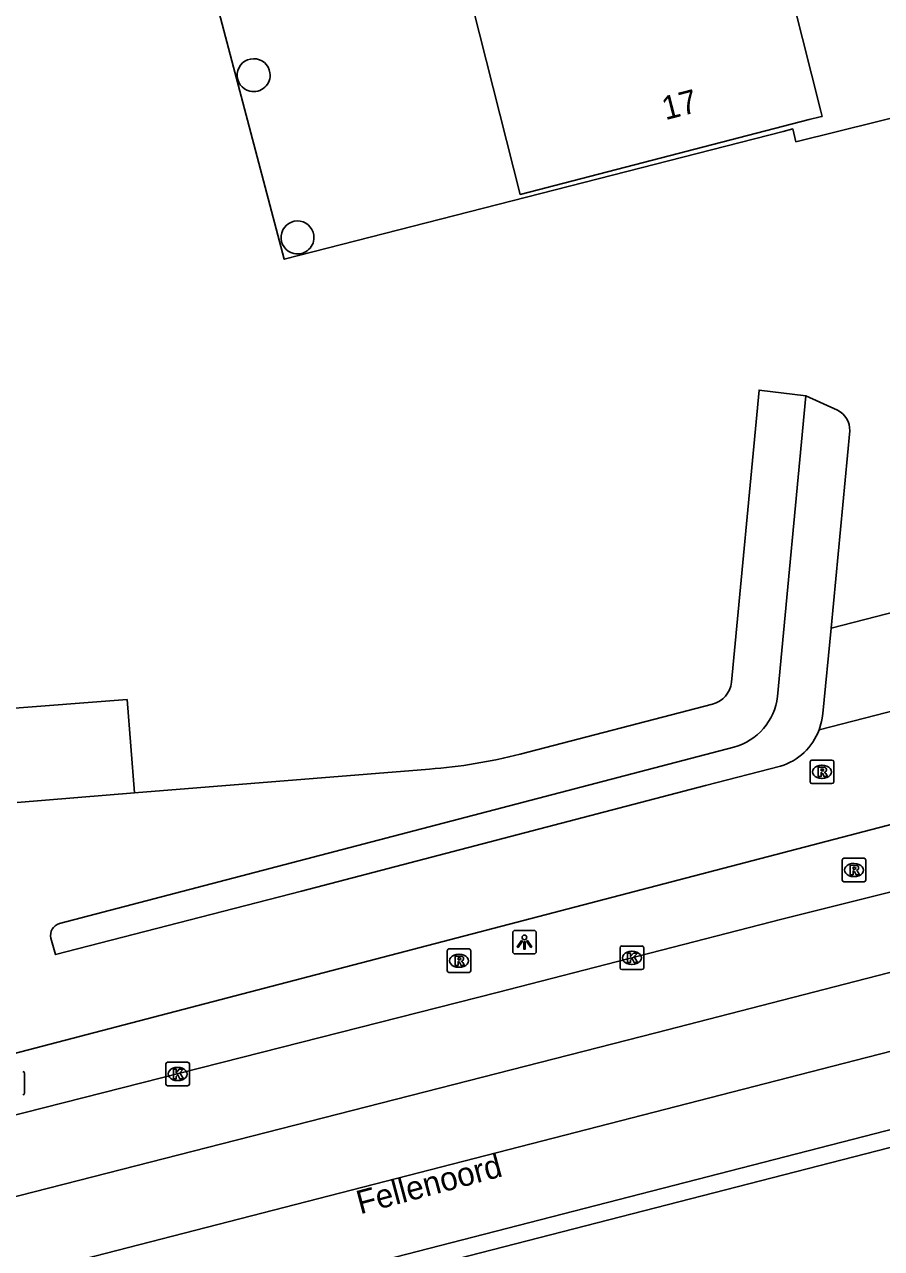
# Model space of a CAD drawing. Extents: x 160806 to 161707, y 383697 to 384148.
# Drawn here: x 161279.8 to 161316.2, y 383941 to 383993.1 of the extents above; entities that cross this region are included whole.
import ezdxf

# ---------------------------------------------------------------- set-up
doc = ezdxf.new("R2010")
doc.units = 0
for name, color, linetype in [('IMGEO_Groenvoorziening', 7, 'Continuous'), ('IMGEO_Hek', 7, 'Continuous'), ('IMGEO_Kolk', 7, 'Continuous'), ('IMGEO_Lichtpunt', 7, 'Continuous'), ('IMGEO_Openbare_ruimte_label', 7, 'Continuous'), ('IMGEO_Pand', 7, 'Continuous'), ('IMGEO_Pand_nummerreeks', 7, 'Continuous'), ('IMGEO_Pand_overbouw', 7, 'Continuous'), ('IMGEO_Rijbaan_lokaal_gesloten', 7, 'Continuous'), ('IMGEO_Rioolput', 7, 'Continuous'), ('IMGEO_Voetpad_gesloten', 7, 'Continuous'), ('IMGEO_Voetpad_op_trap', 7, 'Continuous'), ('IMGEO_Voetpad_open', 7, 'Continuous')]:
    doc.layers.add(name, color=color, linetype=linetype)

msp = doc.modelspace()

# ---------------------------------------------------------------- linework, layer by layer
at = {"layer": 'IMGEO_Groenvoorziening'}
for points in [[(161312.991, 383977.283), (161314.329, 383976.67)], [(161314.852, 383975.798), (161314.058, 383967.401)]]:
    msp.add_lwpolyline(points, dxfattribs=at)
msp.add_arc((161313.922, 383975.833), 0.931, 357.8367, 64.0715, dxfattribs=at)
at = {"layer": 'IMGEO_Hek'}
msp.add_lwpolyline([(161341.247, 383951.682), (161296.689, 383940.215), (161287.043, 383937.692)], dxfattribs=at)
at = {"layer": 'IMGEO_Kolk'}
for p, q in [((161305.096, 383952.97), (161305.096, 383953.822)), ((161305.171, 383953.896), (161306.023, 383953.896)), ((161306.097, 383953.822), (161306.097, 383952.97)), ((161305.584, 383953.676), (161305.609, 383953.676)), ((161306.023, 383952.896), (161305.171, 383952.896)), ((161305.607, 383953.116), (161305.582, 383953.116)), ((161285.793, 383948.03), (161285.793, 383948.882)), ((161285.868, 383948.956), (161286.72, 383948.956)), ((161286.281, 383948.736), (161286.306, 383948.736)), ((161286.794, 383948.882), (161286.794, 383948.03)), ((161286.304, 383948.176), (161286.279, 383948.176)), ((161286.72, 383947.956), (161285.868, 383947.956))]:
    msp.add_line(p, q, dxfattribs=at)
for points in [[(161305.096, 383952.97), (161305.096, 383953.822)], [(161305.171, 383953.896), (161306.023, 383953.896)], [(161306.097, 383953.822), (161306.097, 383952.97)], [(161305.417, 383953.596), (161305.54, 383953.596), (161305.54, 383953.445), (161305.67, 383953.596), (161305.834, 383953.596), (161305.688, 383953.445), (161305.841, 383953.196), (161305.689, 383953.196), (161305.604, 383953.36), (161305.54, 383953.293), (161305.54, 383953.196), (161305.417, 383953.196), (161305.417, 383953.596)], [(161306.023, 383952.896), (161305.171, 383952.896)], [(161285.793, 383948.03), (161285.793, 383948.882)], [(161285.868, 383948.956), (161286.72, 383948.956)], [(161286.114, 383948.656), (161286.237, 383948.656), (161286.237, 383948.505), (161286.367, 383948.656), (161286.531, 383948.656), (161286.385, 383948.505), (161286.538, 383948.256), (161286.386, 383948.256), (161286.301, 383948.42), (161286.237, 383948.353), (161286.237, 383948.256), (161286.114, 383948.256), (161286.114, 383948.656)], [(161286.794, 383948.882), (161286.794, 383948.03)], [(161286.72, 383947.956), (161285.868, 383947.956)]]:
    msp.add_lwpolyline(points, dxfattribs=at)
for centre, start, end in [((161305.173, 383953.82), 91.552, 178.448), ((161305.173, 383953.82), 91.552, 178.448), ((161306.021, 383953.82), 1.552, 88.448), ((161306.021, 383953.82), 1.552, 88.448), ((161305.173, 383952.972), 181.552, 268.448), ((161305.173, 383952.972), 181.552, 268.448), ((161306.021, 383952.972), 271.552, 358.448), ((161306.021, 383952.972), 271.552, 358.448), ((161285.87, 383948.88), 91.552, 178.448), ((161285.87, 383948.88), 91.552, 178.448), ((161286.718, 383948.88), 1.552, 88.448), ((161286.718, 383948.88), 1.552, 88.448), ((161285.87, 383948.032), 181.552, 268.448), ((161285.87, 383948.032), 181.552, 268.448), ((161286.718, 383948.032), 271.552, 358.448), ((161286.718, 383948.032), 271.552, 358.448)]:
    msp.add_arc(centre, 0.0765, start, end, dxfattribs=at)
for centre, major_axis, ratio, start_param, end_param in [((161305.583, 383953.396), (-0.387, 0.002), 0.722429, 4.712389, 7.853982), ((161305.608, 383953.396), (-0.39, 0.002), 0.717154, 1.570796, 4.712389), ((161286.28, 383948.456), (-0.387, 0.002), 0.722429, 4.712389, 7.853982), ((161286.305, 383948.456), (-0.39, 0.002), 0.717154, 1.570796, 4.712389)]:
    msp.add_ellipse(centre, major_axis=major_axis, ratio=ratio, start_param=start_param, end_param=end_param, dxfattribs=at)
at = {"layer": 'IMGEO_Lichtpunt'}
for p, q in [((161300.534, 383954.464), (161300.534, 383953.657)), ((161300.534, 383954.464), (161300.534, 383953.657)), ((161301.436, 383954.559), (161300.628, 383954.559)), ((161301.436, 383954.559), (161300.628, 383954.559)), ((161301.53, 383953.657), (161301.53, 383954.464)), ((161301.53, 383953.657), (161301.53, 383954.464)), ((161300.628, 383953.563), (161301.436, 383953.563)), ((161300.628, 383953.563), (161301.436, 383953.563))]:
    msp.add_line(p, q, dxfattribs=at)
for points in [[(161300.908, 383954.128), (161300.947, 383954.1), (161300.759, 383953.838), (161300.721, 383953.865), (161300.908, 383954.128)], [(161301.01, 383954.08), (161301.057, 383954.08), (161301.057, 383953.758), (161301.01, 383953.758), (161301.01, 383954.08)], [(161301.12, 383954.1), (161301.158, 383954.127), (161301.345, 383953.865), (161301.306, 383953.837), (161301.12, 383954.1)]]:
    msp.add_lwpolyline(points, dxfattribs=at)
msp.add_circle((161301.033, 383954.262), 0.0994, dxfattribs=at)
for centre, start, end in [((161300.628, 383954.464), 90, 180), ((161300.628, 383954.464), 90, 180), ((161301.436, 383954.464), 0, 90), ((161301.436, 383954.464), 0, 90), ((161300.628, 383953.657), 180, 270), ((161300.628, 383953.657), 180, 270), ((161301.436, 383953.657), 270, 0), ((161301.436, 383953.657), 270, 360)]:
    msp.add_arc(centre, 0.0946, start, end, dxfattribs=at)
at = {"layer": 'IMGEO_Pand'}
msp.add_lwpolyline([(161310.919, 384001.335), (161310.658, 384001.268), (161312.108, 383995.404), (161312.338, 383995.464), (161312.682, 383994.096), (161312.451, 383994.037), (161313.62, 383989.378), (161313.677, 383989.154), (161313.593, 383989.134), (161313.129, 383989.019), (161300.843, 383985.84), (161297.111, 384000.629), (161297.354, 384000.692), (161297.319, 384000.838), (161298.032, 384001.03), (161298.073, 384000.878), (161302.412, 384002.002), (161309.96, 384003.959), (161310.329, 384002.536), (161310.591, 384002.604), (161310.919, 384001.335)], dxfattribs=at)
for centre, start, end in [((161289.525, 383990.908), 7.8929, 256.8414), ((161289.526, 383990.908), 256.8144, 7.9199), ((161291.388, 383984.01), 7.8929, 256.8414), ((161291.389, 383984.01), 256.8144, 7.9199)]:
    msp.add_arc(centre, 0.7, start, end, dxfattribs=at)
at = {"layer": 'IMGEO_Pand_overbouw'}
msp.add_lwpolyline([(161286.226, 384000.503), (161290.822, 383983.081), (161312.031, 383988.52), (161312.432, 383988.623), (161312.567, 383988.079), (161331.698, 383992.825), (161336.907, 383994.117)], dxfattribs=at)
at = {"layer": 'IMGEO_Rijbaan_lokaal_gesloten'}
for points in [[(161270.989, 383941.101), (161306.607, 383950.212), (161339.296, 383958.642), (161362.907, 383964.706), (161409.072, 383976.597), (161453.394, 383987.997), (161464.472, 383990.836)], [(161271.807, 383937.9), (161315.559, 383949.156), (161335.194, 383954.191), (161340.223, 383955.497), (161347.001, 383957.235), (161378.316, 383965.298), (161419.642, 383975.931), (161451.011, 383984.005), (161465.227, 383987.648)], [(161279.919, 383936.647), (161341.031, 383952.394), (161450.194, 383980.461), (161453.055, 383981.256), (161455.902, 383982.36), (161465.14, 383986.182)], [(161401.441, 383978.166), (161395.335, 383976.49), (161389.261, 383974.862), (161383.779, 383973.426), (161378.799, 383972.171), (161373.257, 383970.696), (161367.616, 383969.283), (161361.07, 383967.572), (161355.478, 383966.108), (161350.158, 383964.769), (161340.058, 383962.163), (161335.931, 383961.064), (161335.793, 383961.02), (161335.609, 383960.98), (161332.308, 383960.13), (161327.259, 383958.907), (161322.038, 383957.557), (161317.913, 383956.519), (161311.972, 383955.039), (161299.869, 383951.918), (161276.409, 383945.95)]]:
    msp.add_lwpolyline(points, dxfattribs=at)
at = {"layer": 'IMGEO_Rioolput'}
for p, q in [((161313.172, 383960.873), (161313.172, 383961.725)), ((161313.247, 383961.799), (161314.099, 383961.799)), ((161313.66, 383961.579), (161313.685, 383961.579)), ((161314.173, 383961.725), (161314.173, 383960.873)), ((161313.683, 383961.019), (161313.658, 383961.019)), ((161314.099, 383960.799), (161313.247, 383960.799)), ((161314.534, 383956.699), (161314.534, 383957.551)), ((161314.609, 383957.625), (161315.461, 383957.625)), ((161315.022, 383957.405), (161315.047, 383957.405)), ((161315.535, 383957.551), (161315.535, 383956.699)), ((161315.045, 383956.845), (161315.02, 383956.845)), ((161315.461, 383956.625), (161314.609, 383956.625)), ((161297.749, 383952.844), (161297.749, 383953.696)), ((161297.824, 383953.77), (161298.676, 383953.77)), ((161298.75, 383953.696), (161298.75, 383952.844)), ((161298.237, 383953.55), (161298.262, 383953.55)), ((161298.676, 383952.77), (161297.824, 383952.77)), ((161298.26, 383952.99), (161298.235, 383952.99)), ((161279.787, 383948.493), (161279.787, 383947.641))]:
    msp.add_line(p, q, dxfattribs=at)
for points in [[(161313.172, 383960.873), (161313.172, 383961.725)], [(161313.247, 383961.799), (161314.099, 383961.799)], [(161313.761, 383961.497), (161313.509, 383961.499), (161313.509, 383961.099)], [(161314.173, 383961.725), (161314.173, 383960.873)], [(161313.509, 383961.099), (161313.633, 383961.099), (161313.633, 383961.261), (161313.644, 383961.261)], [(161313.687, 383961.418), (161313.633, 383961.418), (161313.633, 383961.337)], [(161313.633, 383961.337), (161313.685, 383961.337)], [(161313.691, 383961.232), (161313.762, 383961.099), (161313.902, 383961.099), (161313.837, 383961.225)], [(161314.099, 383960.799), (161313.247, 383960.799)], [(161314.534, 383956.699), (161314.534, 383957.551)], [(161314.609, 383957.625), (161315.461, 383957.625)], [(161315.535, 383957.551), (161315.535, 383956.699)], [(161315.123, 383957.323), (161314.871, 383957.325), (161314.871, 383956.925)], [(161314.871, 383956.925), (161314.995, 383956.925), (161314.995, 383957.087), (161315.006, 383957.087)], [(161315.049, 383957.244), (161314.995, 383957.244), (161314.995, 383957.163)], [(161314.995, 383957.163), (161315.047, 383957.163)], [(161315.053, 383957.058), (161315.124, 383956.925), (161315.264, 383956.925), (161315.199, 383957.051)], [(161315.461, 383956.625), (161314.609, 383956.625)], [(161297.749, 383952.844), (161297.749, 383953.696)], [(161297.824, 383953.77), (161298.676, 383953.77)], [(161298.75, 383953.696), (161298.75, 383952.844)], [(161298.338, 383953.468), (161298.086, 383953.47), (161298.086, 383953.07)], [(161298.086, 383953.07), (161298.21, 383953.07), (161298.21, 383953.232), (161298.221, 383953.232)], [(161298.264, 383953.389), (161298.21, 383953.389), (161298.21, 383953.308)], [(161298.21, 383953.308), (161298.262, 383953.308)], [(161298.268, 383953.203), (161298.339, 383953.07), (161298.479, 383953.07), (161298.414, 383953.196)], [(161298.676, 383952.77), (161297.824, 383952.77)], [(161279.787, 383948.493), (161279.787, 383947.641)]]:
    msp.add_lwpolyline(points, dxfattribs=at)
for centre, radius, start, end in [((161313.249, 383961.723), 0.0765, 91.552, 178.448), ((161313.249, 383961.723), 0.0765, 91.552, 178.448), ((161314.097, 383961.723), 0.0765, 1.552, 88.448), ((161314.097, 383961.723), 0.0765, 1.552, 88.448), ((161313.643, 383961.208), 0.0533, 26.0293, 88.6989), ((161313.669, 383961.526), 0.19, 274.7715, 282.9687), ((161313.693, 383961.322), 0.0964, 77.0061, 93.1865), ((161313.707, 383961.379), 0.0378, 276.6634, 79.6772), ((161313.76, 383961.387), 0.109, 350.3612, 89.416), ((161313.758, 383961.387), 0.112, 277.5842, 350.9817), ((161313.742, 383961.172), 0.108, 29.5134, 73.7905), ((161313.249, 383960.875), 0.0765, 181.552, 268.448), ((161313.249, 383960.875), 0.0765, 181.552, 268.448), ((161314.097, 383960.875), 0.0765, 271.552, 358.448), ((161314.097, 383960.875), 0.0765, 271.552, 358.448), ((161314.611, 383957.549), 0.0765, 91.552, 178.448), ((161314.611, 383957.549), 0.0765, 91.552, 178.448), ((161315.459, 383957.549), 0.0765, 1.552, 88.448), ((161315.459, 383957.549), 0.0765, 1.552, 88.448), ((161315.005, 383957.034), 0.0533, 26.0293, 88.6989), ((161315.031, 383957.352), 0.19, 274.7715, 282.9687), ((161315.055, 383957.148), 0.0964, 77.0061, 93.1865), ((161315.069, 383957.205), 0.0378, 276.6634, 79.6772), ((161315.122, 383957.213), 0.109, 350.3612, 89.416), ((161315.12, 383957.213), 0.112, 277.5842, 350.9817), ((161315.104, 383956.998), 0.108, 29.5134, 73.7905), ((161314.611, 383956.701), 0.0765, 181.552, 268.448), ((161314.611, 383956.701), 0.0765, 181.552, 268.448), ((161315.459, 383956.701), 0.0765, 271.552, 358.448), ((161315.459, 383956.701), 0.0765, 271.552, 358.448), ((161297.826, 383953.694), 0.0765, 91.552, 178.448), ((161297.826, 383953.694), 0.0765, 91.552, 178.448), ((161298.674, 383953.694), 0.0765, 1.552, 88.448), ((161298.674, 383953.694), 0.0765, 1.552, 88.448), ((161298.22, 383953.179), 0.0533, 26.0293, 88.6989), ((161298.246, 383953.497), 0.19, 274.7715, 282.9687), ((161298.27, 383953.293), 0.0964, 77.0061, 93.1865), ((161298.284, 383953.35), 0.0378, 276.6634, 79.6772), ((161298.337, 383953.358), 0.109, 350.3612, 89.416), ((161298.335, 383953.358), 0.112, 277.5842, 350.9817), ((161298.319, 383953.143), 0.108, 29.5134, 73.7905), ((161297.826, 383952.846), 0.0765, 181.552, 268.448), ((161297.826, 383952.846), 0.0765, 181.552, 268.448), ((161298.674, 383952.846), 0.0765, 271.552, 358.448), ((161298.674, 383952.846), 0.0765, 271.552, 358.448), ((161279.711, 383948.491), 0.0765, 1.552, 88.448), ((161279.711, 383948.491), 0.0765, 1.552, 88.448), ((161279.711, 383947.643), 0.0765, 271.552, 358.448), ((161279.711, 383947.643), 0.0765, 271.552, 358.448)]:
    msp.add_arc(centre, radius, start, end, dxfattribs=at)
for centre, major_axis, ratio, start_param, end_param in [((161313.659, 383961.299), (-0.387, 0.002), 0.722429, 4.712389, 7.853982), ((161313.684, 383961.299), (-0.39, 0.002), 0.717154, 1.570796, 4.712389), ((161315.021, 383957.125), (-0.387, 0.002), 0.722429, 4.712389, 7.853982), ((161315.046, 383957.125), (-0.39, 0.002), 0.717154, 1.570796, 4.712389), ((161298.236, 383953.27), (-0.387, 0.002), 0.722429, 4.712389, 7.853982), ((161298.261, 383953.27), (-0.39, 0.002), 0.717154, 1.570796, 4.712389)]:
    msp.add_ellipse(centre, major_axis=major_axis, ratio=ratio, start_param=start_param, end_param=end_param, dxfattribs=at)
at = {"layer": 'IMGEO_Voetpad_gesloten'}
for points in [[(161278.831, 383963.961), (161284.147, 383964.369), (161284.463, 383960.399)], [(161279.47, 383959.995), (161284.463, 383960.399)]]:
    msp.add_lwpolyline(points, dxfattribs=at)
at = {"layer": 'IMGEO_Voetpad_op_trap'}
for points in [[(161314.058, 383967.401), (161320.231, 383968.987)], [(161314.058, 383967.401), (161313.715, 383963.777), (161313.686, 383963.573), (161313.66, 383963.436), (161313.55, 383963.082)]]:
    msp.add_lwpolyline(points, dxfattribs=at)
at = {"layer": 'IMGEO_Voetpad_open'}
for points in [[(161430.551, 383993.434), (161414.805, 383989.287), (161369.289, 383977.37), (161370.444, 383973.147), (161318.287, 383959.498), (161275.829, 383948.409)], [(161309.829, 383965.107), (161311.003, 383977.521), (161312.991, 383977.283)], [(161312.991, 383977.283), (161311.782, 383964.497)], [(161313.55, 383963.082), (161319.775, 383964.679)], [(161300.843, 383962.049), (161309.022, 383964.174)], [(161309.928, 383962.353), (161281.272, 383954.848)], [(161280.914, 383954.227), (161281.104, 383953.53), (161291.557, 383956.232), (161308.729, 383960.719), (161311.907, 383961.542)], [(161284.463, 383960.399), (161296.995, 383961.414)]]:
    msp.add_lwpolyline(points, dxfattribs=at)
for centre, radius, start, end in [((161308.738, 383965.236), 1.099, 285.0011, 353.2824), ((161309.286, 383964.782), 2.513, 284.8118, 353.4857), ((161311.208, 383963.934), 2.492, 286.2888, 340.0044), ((161295.251, 383983.958), 22.612, 274.4233, 284.3178), ((161281.415, 383954.352), 0.517, 106.1159, 193.9581)]:
    msp.add_arc(centre, radius, start, end, dxfattribs=at)

# ---------------------------------------------------------------- texts
at = {"layer": 'IMGEO_Openbare_ruimte_label'}
msp.add_text('Fellenoord', height=1, rotation=14.9536, dxfattribs=at).set_placement((161294.05, 383942.49))
at = {"layer": 'IMGEO_Pand_nummerreeks'}
msp.add_text('17', height=1, rotation=14.3068, dxfattribs=at).set_placement((161307.02, 383988.991))

doc.saveas('drawing.dxf')
